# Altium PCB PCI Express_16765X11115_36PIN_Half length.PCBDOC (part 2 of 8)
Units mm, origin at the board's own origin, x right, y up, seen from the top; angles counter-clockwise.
Board outline 178 x 110.97 mm, 10 copper layers (Top Layer, Int1 (GND), Int2 (Sign), Int3 (Sign), Int4 (PWR), Int5 (GND), Int6 (Sign), Int7 (Sign), Int8 (GND), Bottom Layer), stack 1.429 mm thick; 528 components, 525 nets, 2272 pads, 1491 vias.
Unrouted connection lines stored in the file: 373.
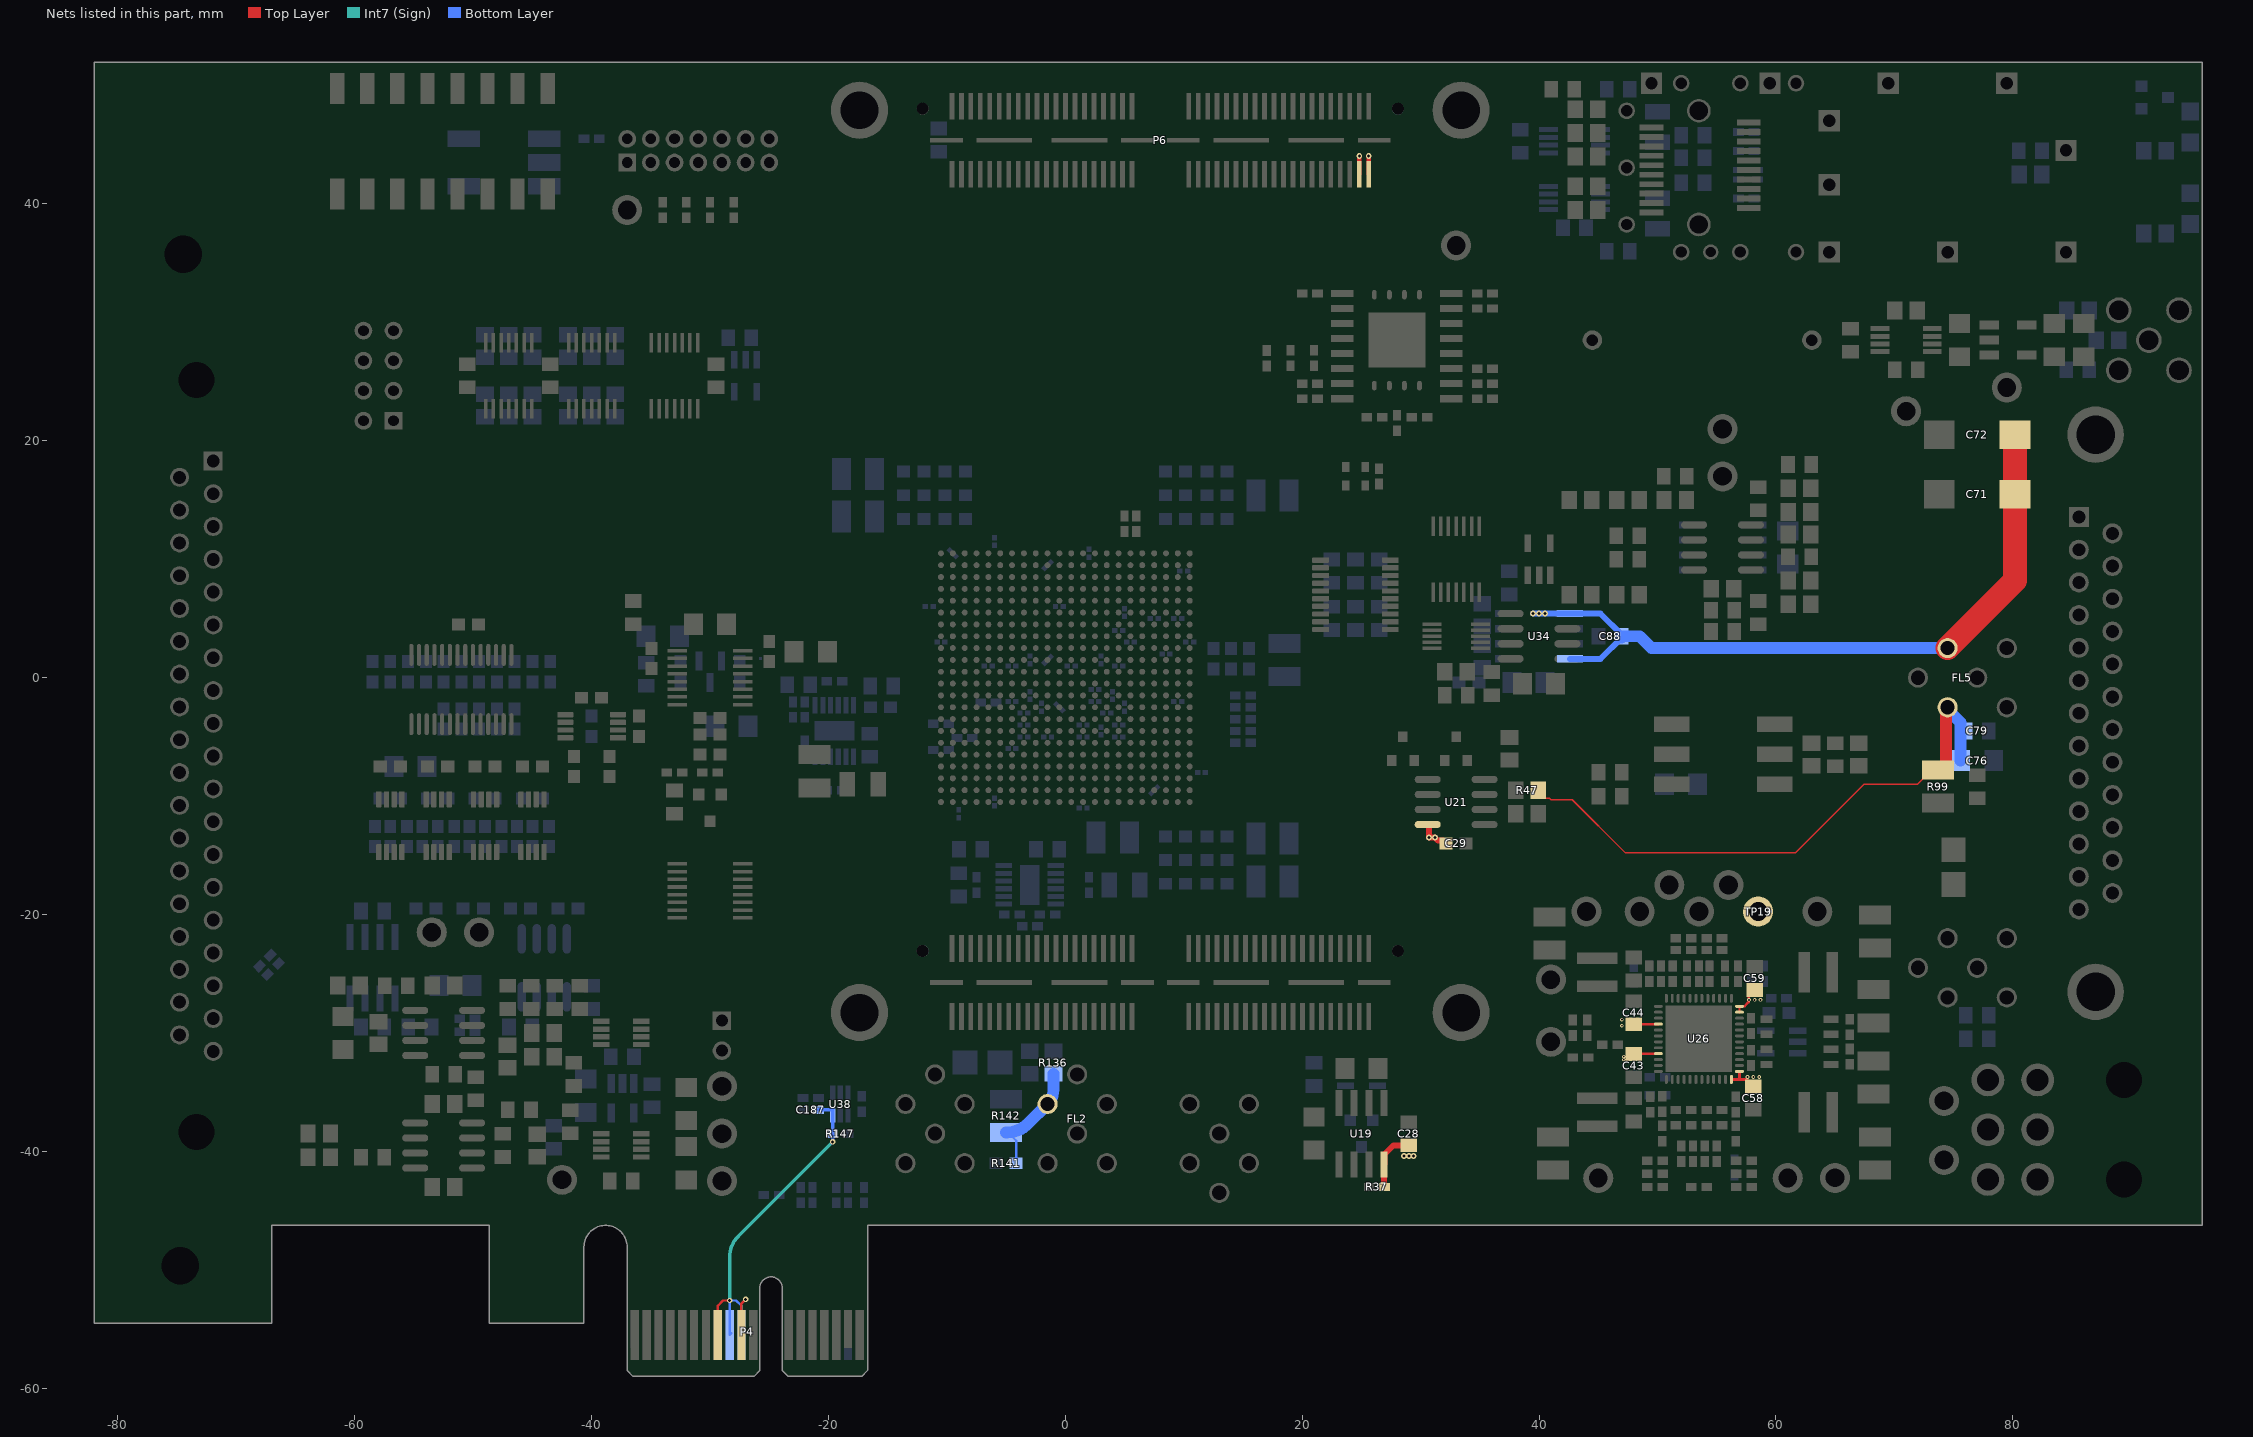
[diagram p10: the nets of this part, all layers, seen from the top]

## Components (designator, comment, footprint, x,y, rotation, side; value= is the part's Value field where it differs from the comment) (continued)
U10 "74LVC04" TSSOP14 -40,25.5 r0 top locked (schematic designator U25)
U11 "AD5060" SSO-G8/SM8 -37.5,-39.5 r270 top (schematic designator U45)
U12 "AD5060" SSO-G8/SM8 -37.5,-30 r270 top (schematic designator U14)
U13 "74LVC74D" TSSOP14 -33,25.5 r180 top (schematic designator U22)
U14 "SN65LVDT390" TSSOP16 -30,-18 r90 top (schematic designator U46)
U15 "SN74LVC4T245" TSSOP16 -30,0 r270 top (schematic designator U29)
U16 "XC7A35T-2FGG484C" FGG484 0,0 r90 top locked (schematic designator U18)
U17 "SN65LVDT14QPWREP" PW0020A_N 24.5,7 r0 top (schematic designator U6)
U18 "S25FL128SAGMFI001" FP-002-15547-MFG 28,28 r180 top locked (schematic designator U13)
U19 "LTC1144" SO-G8 25,-38.5 r180 top (schematic designator U50)
U20 "S25FL128SAGNFI003" SPSN-WSON-8_L 28,28.5 r270 top locked (schematic designator U16)
U21 "OP284ES" ADI-R-8_N 33,-10.5 r180 top (schematic designator U34)
U22 "AD7685" TSSO3x5-G10 33,3.5 r90 top (schematic designator U7)
U23 "74LVC74D" TSSOP14 33,10 r180 top (schematic designator U9)
U24 "OP284ES" SO-8_N 40,3.5 r180 top (schematic designator U5)
U25 "SN74LVC1G00" SO-G5/E2.4 40,10 r0 top (schematic designator U12)
U26 "ADP5050ACPZ-R7" CP-48-13_L 53.5,-30.5 r0 top value=Value (schematic designator U31)
U27 "33.554432MHz" VECTRON_C5310 59.9,-9 r180 top (schematic designator U10)
U28 "OP284ES" SO-8_N 55.5,11 r0 top (schematic designator U11)
U29 "SN65LVDS100D" MSOP8 71,28.5 r90 top (schematic designator U17)
U30 "SN65LVDT2" SO-G5/E2.4 60.5,-30.75 r270 bottom (schematic designator U15)
U31 "ADR425BR" SO-G8 55.5,11 r270 bottom (schematic designator U3)
U32 "SN65LVDS100D" MSOP8 43,45.3 r270 bottom (schematic designator U4)
U33 "SN65LVDT101D" MSOP8 43,40.5 r90 bottom (schematic designator U8)
U34 "LT1763" SO-G8 40,3.5 r90 bottom (schematic designator U1)
U35 "SN65LVDT2" SO-G5/E2.4 25,-33.5 r90 bottom (schematic designator U30)
U36 "LT3045" MSOP12_PAD -3,-17.5 r180 bottom (schematic designator U19)
U37 "LT3045" MSOP12_PAD -19.5,-4.5 r90 bottom locked (schematic designator U20)
U38 "SN74AVC1T45" SC70 -19,-36 r0 bottom (schematic designator U23)
U39 "SN65LVDT2" SO-G5/E2.4 -27,25.5 r0 bottom (schematic designator U24)
U40 "REF3033AIDBZRG4" TI-DBZ3_N -30,0.5 r270 bottom (schematic designator U33)
U41 "LT1964ES5-5" LT-S5-5-TSOT-23_M -37.4,-35.5 r270 bottom (schematic designator U49)
U42 "ADR421ARZ" ADI-R-8_M -44,-24.5 r270 bottom (schematic designator U51)
U43 "LT1763" SO-G8 -58.5,-24.5 r180 bottom (schematic designator U48)
W1 "Net tie" NETTIE1_BOTH -29,-28.96 r270 top net-tie (schematic designator W2)
W2 "Net tie" NETTIE1_SMDTOP -25.75,1.625 r0 bottom net-tie (schematic designator W3)
Y1 "DSC1001DI1-025.0000T" FP-CDFN2520-4LD-PL-1-MFG 24.493,17.003 r270 top

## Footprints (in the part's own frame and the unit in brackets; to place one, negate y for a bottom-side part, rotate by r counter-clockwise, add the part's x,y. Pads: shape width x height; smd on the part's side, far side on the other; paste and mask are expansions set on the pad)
2MM_HDR2X7_RA [mm] "Connector; 2mm Header; 7x2 Position, RA"
  rect 1.5x1.5 hole 0.9: 1(0,0)
  round 1.5 hole 0.9: 2(0,2) 3(2,0) 4(2,2) 5(4,0) 6(4,2) 7(6,0) 8(6,2) 9(8,0) 10(8,2) 11(10,0) 12(10,2) 13(12,0) 14(12,2)
  silkscreen extent -2.29,-1.27 14.22,8.38, body extent -2.32,-0.27 14.33,8.38, height 6.3
455580003 [mm]
  round 2.775 hole 1.85: 1(0,0) 2(4.191,0) 3(8.4,0) 4(0,-4.2) 5(4.2,-4.2) 6(8.4,-4.2)
  round 1.525 hole 3.05 unplated: MH1(0,7.3) MH2(8.4,7.3)
  silkscreen extent -2.7,1.1 11.1,13.9, body extent -3.14,-4.78 11.06,13.86, height 11.53
9181089621 [mm] "Connector; IDC, PCB Transition - 2 Rows, Thru-Hole; 8 Position; Vertical; Pitch 2.54 mm; Body 15.46 x 6.1 x 7.45 mm (LxWxH)"
  rect 1.5x1.5 hole 0.9: 1(-3.81,-1.27)
  round 1.5 hole 0.9: 2(-3.81,1.27) 3(-1.27,-1.27) 4(-1.27,1.27) 5(1.27,-1.27) 6(1.27,1.27) 7(3.81,-1.27) 8(3.81,1.27)
  silkscreen extent -7.73,-3.83 7.73,3.05
ADI-R-8_M [mm] "SOIC, 8-Leads, Body 4.9x3.9mm, Pitch 1.27mm, IPC Low Density"
  oval 2.5x0.7 smd: 1(-2.45,1.905) 2(-2.45,0.635) 3(-2.45,-0.635) 4(-2.45,-1.905) 5(2.45,-1.905) 6(2.45,-0.635) 7(2.45,0.635) 8(2.45,1.905)
  silkscreen extent -2.57,-2.5 0.8,2.93, body extent -2,-2.5 2,2.5, height 1.75
ADI-R-8_N [mm] "SOIC, 8-Leads, Body 4.9x3.9mm, Pitch 1.27mm, IPC Medium Density"
  oval 2.2x0.6 smd: 1(-2.4,1.905) 2(-2.4,0.635) 3(-2.4,-0.635) 4(-2.4,-1.905) 5(2.4,-1.905) 6(2.4,-0.635) 7(2.4,0.635) 8(2.4,1.905)
  silkscreen extent -2.53,-2.5 0.9,2.88, body extent -2,-2.5 2,2.5, height 1.75
ADI-RU-28_M [mm] "SOP, 28-Leads, Body 9.7x4.4mm, Pitch 0.65mm, IPC Low Density"
  oval 1.85x0.35 smd: 1(-2.925,4.225) 2(-2.925,3.575) 3(-2.925,2.925) 4(-2.925,2.275) 5(-2.925,1.625) 6(-2.925,0.975) 7(-2.925,0.325) 8(-2.925,-0.325) 9(-2.925,-0.975) 10(-2.925,-1.625) 11(-2.925,-2.275) 12(-2.925,-2.925) 13(-2.925,-3.575) 14(-2.925,-4.225) 15(2.925,-4.225) 16(2.925,-3.575) 17(2.925,-2.925) 18(2.925,-2.275) 19(2.925,-1.625) 20(2.925,-0.975) 21(2.925,-0.325) 22(2.925,0.325) 23(2.925,0.975) 24(2.925,1.625) 25(2.925,2.275) 26(2.925,2.925) 27(2.925,3.575) 28(2.925,4.225)
  silkscreen extent -3.05,-4.9 1.6,5.08, body extent -2.25,-4.9 2.25,4.9, height 1.2
AT224-3 [mil] "Mini-Circuits transformer"
  rect 65x30 smd: 1(0,-100) 2(0,-50) 3(0,0) 4(125,0) 6(125,-100)
  silkscreen extent 25,-135 100,-135, body extent 0,-125 125,25, height 150
CA053035 [mil] "Axial film capacitor, Size 0.53\"(L) x 0.35\"(D)"
  round 65 hole 38: 1(0,0) 2(730,0)
  silkscreen extent 40,-175 690,175, body extent 80,-175 650,175, height 360
CAPC0603X33X15NL03T05 [mm] "Chip Capacitor, 2-Leads, Body 0.60x0.30mm, IPC Medium Density"
  rect 0.46x0.42 smd: 1(-0.33,0) 2(0.33,0)
  body extent -0.31,-0.17 0.32,0.16, height 0.33
CC1005-0402 [mm] "Chip Capacitor; Body 1.0 x 0.5 mm (LxW typ)"
  rect 0.9x0.7 smd: 1(-0.65,0) 2(0.65,0)
  silkscreen extent -1.4,-0.25 -1.4,0.25, body extent -0.53,-0.28 0.52,0.27, height 0.55
CC1608-0603 [mm] "Chip Capacitor; Body 1.6 x 0.8 mm (LxW typ)"
  rect 1.1x1 smd: 1(-0.85,0) 2(0.85,0)
  silkscreen extent -1.7,-0.4 -1.7,0.4, body extent -0.87,-0.48 0.87,0.48, height 0.87
CC2013-0805 [mm] "Chip Capacitor; Body 2.0 x 1.3 mm (LxW typ)"
  rect 1.15x1.4 smd: 1(-0.975,0) 2(0.975,0)
  silkscreen extent -1.85,-0.6 -1.85,0.6, body extent -1.1,-0.73 1.1,0.72, height 0.88
CC3216-1206 [mm] "Chip Capacitor; Body 3.2 x 1.6 mm (LxW typ)"
  rect 1.6x1.8 smd: 1(-1.4,0) 2(1.4,0)
  silkscreen extent -0.3,-0.8 0.3,0.8, body extent -1.85,-0.98 1.85,0.97, height 0.88
CC3225-1210 [mm] "Chip Capacitor; Body 3.2 x 2.5 mm (LxW typ)"
  rect 1.6x2.7 smd: 1(-1.4,0) 2(1.4,0)
  silkscreen extent -0.3,-1.25 0.3,1.25, body extent -1.85,-1.45 1.85,1.45, height 1.4
CL2520-1008 [mm] "Chip Inductor; Body 2.54 x 2.0 mm (LxW typ)"
  rect 1.3x2.1 smd: 1(-1.3,0) 2(1.3,0)
  silkscreen extent -2.25,-1 -2.25,1, body extent -1.46,-1.39 1.46,1.4, height 2.02
CP-48-13_L [mm] "QFN, 48-Leads, Body 7x7mm, Pitch 0.5mm, Thermal Pad 5.6x5.6mm, IPC High Density"
  oval 0.75x0.25 smd: 1(-3.425,2.75) 2(-3.425,2.25) 3(-3.425,1.75) 4(-3.425,1.25) 5(-3.425,0.75) 6(-3.425,0.25) 7(-3.425,-0.25) 8(-3.425,-0.75) 9(-3.425,-1.25) 10(-3.425,-1.75) 11(-3.425,-2.25) 12(-3.425,-2.75) 25(3.425,-2.75) 26(3.425,-2.25) 27(3.425,-1.75) 28(3.425,-1.25) 29(3.425,-0.75) 30(3.425,-0.25) 31(3.425,0.25) 32(3.425,0.75) 33(3.425,1.25) 34(3.425,1.75) 35(3.425,2.25) 36(3.425,2.75)
  oval 0.25x0.75 smd: 13(-2.75,-3.425) 14(-2.25,-3.425) 15(-1.75,-3.425) 16(-1.25,-3.425) 17(-0.75,-3.425) 18(-0.25,-3.425) 19(0.25,-3.425) 20(0.75,-3.425) 21(1.25,-3.425) 22(1.75,-3.425) 23(2.25,-3.425) 24(2.75,-3.425) 37(2.75,3.425) 38(2.25,3.425) 39(1.75,3.425) 40(1.25,3.425) 41(0.75,3.425) 42(0.25,3.425) 43(-0.25,3.425) 44(-0.75,3.425) 45(-1.25,3.425) 46(-1.75,3.425) 47(-2.25,3.425) 48(-2.75,3.425)
  rect 5.6x5.6 smd: 49(0,0)
  silkscreen extent -4.47,-3.7 3.7,3.7, body extent -3.55,-3.55 3.55,3.55, height 0.8
CR1005-0402 [mm] "Chip Resistor; Body 1.1 x 0.5 mm (LxW typ)"
  rect 0.9x0.7 smd: 1(-0.65,0) 2(0.65,0)
  body extent -0.5,-0.25 0.5,0.25, height 0.32
CR1608-0603 [mm] "Chip Resistor; Body 1.6 x 0.8 mm (LxW typ)"
  rect 1.1x1 smd: 1(-0.85,0) 2(0.85,0)
  body extent -0.76,-0.43 0.79,0.42, height 0.46
CR2012-0805 [mm] "Chip Resistor; Body 2.0 x 1.3 mm (LxW typ)"
  rect 1.3x1.5 smd: 1(-0.95,0) 2(0.95,0)
  body extent -1,-0.62 1,0.63, height 0.46
CR3216-1206 [mm] "Chip Resistor; Body 3.2 x 1.6 mm (LxW typ)"
  rect 1.6x1.8 smd: 1(-1.4,0) 2(1.4,0)
  silkscreen extent -0.3,-0.8 0.3,0.8, body extent -1.67,-0.86 1.68,0.87, height 0.85
CR3225-1210 [mm] "Chip Resistor; Body 3.2 x 2.5 mm (LxW typ)"
  rect 1.6x2.7 smd: 1(-1.4,0) 2(1.4,0)
  silkscreen extent -0.3,-1.25 0.3,1.25, body extent -1.73,-1.37 1.73,1.37, height 0.71
DB25F-RA [mm] "Receptiacle; D Subminiature 25 Position; Right Angle"
  rect 1.69x1.69 hole 1.09: 1(-16.566,-1.42)
  round 1.69 hole 1.09: 2(-13.805,-1.42) 3(-11.044,-1.42) 4(-8.283,-1.42) 5(-5.522,-1.42) 6(-2.761,-1.42) 7(0,-1.42) 8(2.761,-1.42) 9(5.522,-1.42) 10(8.283,-1.42) 11(11.044,-1.42) 12(13.805,-1.42) 13(16.566,-1.42) 14(-15.185,1.42) 15(-12.424,1.42) 16(-9.663,1.42) 17(-6.902,1.42) 18(-4.142,1.42) 19(-1.381,1.42) 20(1.381,1.42) 21(4.142,1.42) 22(6.903,1.42) 23(9.664,1.42) 24(12.425,1.42) 25(15.186,1.42)
  round 4.76 hole 3.26: 26(-23.526,0) 27(23.526,0)
  silkscreen extent -26.5,-3 26.6,9.5, body extent -26.59,-3.18 26.49,15.72, height 12.62
DGK0008A_N [mm] "TSOP, 8-Leads, Body 3.1x3.1mm, Pitch 0.65mm, IPC Medium Density"
  rrect22% 1.35x0.45 smd: 1(-2.225,0.975) 2(-2.225,0.325) 3(-2.225,-0.325) 4(-2.225,-0.975) 5(2.225,-0.975) 6(2.225,-0.325) 7(2.225,0.325) 8(2.225,0.975)
  silkscreen extent -2.35,-1.55 1.15,1.9, body extent -2.45,-1.5 2.45,1.5, height 0.94
DIP_SW_8WAY_SMD_SIDE [mm] "DIP Switch; 16 Leads, right-angle"
  rect 1.2x2.6 smd: 1(-8.89,-4.45) 2(-6.35,-4.45) 3(-3.81,-4.45) 4(-1.27,-4.45) 5(1.27,-4.45) 6(3.81,-4.45) 7(6.35,-4.45) 8(8.89,-4.45) 9(8.89,4.45) 10(6.35,4.45) 11(3.81,4.45) 12(1.27,4.45) 13(-1.27,4.45) 14(-3.81,4.45) 15(-6.35,4.45) 16(-8.89,4.45)
  silkscreen extent -10.29,-2.5 10.31,2.5, body extent -11.15,-6.5 11.15,4.65, height 6.98
FGG484 [mm] "BGA, 484-Balls, Body 23x23mm, Pitch 1mm"
  round 0.5 smd: A1(-10.5,10.5) A2(-9.5,10.5) A3(-8.5,10.5) A4(-7.5,10.5) A5(-6.5,10.5) A6(-5.5,10.5) A7(-4.5,10.5) A8(-3.5,10.5) A9(-2.5,10.5) A10(-1.5,10.5) A11(-0.5,10.5) A12(0.5,10.5) A13(1.5,10.5) A14(2.5,10.5) A15(3.5,10.5) A16(4.5,10.5) A17(5.5,10.5) A18(6.5,10.5) A19(7.5,10.5) A20(8.5,10.5) A21(9.5,10.5) A22(10.5,10.5) AA1(-10.5,-9.5) AA2(-9.5,-9.5) AA3(-8.5,-9.5) AA4(-7.5,-9.5) AA5(-6.5,-9.5) AA6(-5.5,-9.5) AA7(-4.5,-9.5) AA8(-3.5,-9.5) AA9(-2.5,-9.5) AA10(-1.5,-9.5) AA11(-0.5,-9.5) AA12(0.5,-9.5) AA13(1.5,-9.5) AA14(2.5,-9.5) AA15(3.5,-9.5) AA16(4.5,-9.5) AA17(5.5,-9.5) AA18(6.5,-9.5) AA19(7.5,-9.5) AA20(8.5,-9.5) AA21(9.5,-9.5) AA22(10.5,-9.5) AB1(-10.5,-10.5) AB2(-9.5,-10.5) AB3(-8.5,-10.5) AB4(-7.5,-10.5) AB5(-6.5,-10.5) AB6(-5.5,-10.5) AB7(-4.5,-10.5) AB8(-3.5,-10.5) AB9(-2.5,-10.5) AB10(-1.5,-10.5) AB11(-0.5,-10.5) AB12(0.5,-10.5) AB13(1.5,-10.5) AB14(2.5,-10.5) AB15(3.5,-10.5) AB16(4.5,-10.5) AB17(5.5,-10.5) AB18(6.5,-10.5) AB19(7.5,-10.5) AB20(8.5,-10.5) AB21(9.5,-10.5) AB22(10.5,-10.5) B1(-10.5,9.5) B2(-9.5,9.5) B3(-8.5,9.5) B4(-7.5,9.5) B5(-6.5,9.5) B6(-5.5,9.5) B7(-4.5,9.5) B8(-3.5,9.5) B9(-2.5,9.5) B10(-1.5,9.5) B11(-0.5,9.5) B12(0.5,9.5) B13(1.5,9.5) B14(2.5,9.5) B15(3.5,9.5) B16(4.5,9.5) B17(5.5,9.5) B18(6.5,9.5) B19(7.5,9.5) B20(8.5,9.5) B21(9.5,9.5) B22(10.5,9.5) C1(-10.5,8.5) C2(-9.5,8.5) C3(-8.5,8.5) C4(-7.5,8.5) C5(-6.5,8.5) C6(-5.5,8.5) C7(-4.5,8.5) C8(-3.5,8.5) C9(-2.5,8.5) C10(-1.5,8.5) C11(-0.5,8.5) C12(0.5,8.5) C13(1.5,8.5) C14(2.5,8.5) C15(3.5,8.5) C16(4.5,8.5) C17(5.5,8.5) C18(6.5,8.5) C19(7.5,8.5) C20(8.5,8.5) C21(9.5,8.5) C22(10.5,8.5) D1(-10.5,7.5) D2(-9.5,7.5) D3(-8.5,7.5) D4(-7.5,7.5) D5(-6.5,7.5) D6(-5.5,7.5) D7(-4.5,7.5) D8(-3.5,7.5) D9(-2.5,7.5) D10(-1.5,7.5) D11(-0.5,7.5) D12(0.5,7.5) D13(1.5,7.5) D14(2.5,7.5) D15(3.5,7.5) D16(4.5,7.5) D17(5.5,7.5) D18(6.5,7.5) D19(7.5,7.5) D20(8.5,7.5) D21(9.5,7.5) D22(10.5,7.5) E1(-10.5,6.5) E2(-9.5,6.5) E3(-8.5,6.5) E4(-7.5,6.5) E5(-6.5,6.5) E6(-5.5,6.5) E7(-4.5,6.5) E8(-3.5,6.5) E9(-2.5,6.5) E10(-1.5,6.5) E11(-0.5,6.5) E12(0.5,6.5) E13(1.5,6.5) E14(2.5,6.5) E15(3.5,6.5) E16(4.5,6.5) E17(5.5,6.5) E18(6.5,6.5) E19(7.5,6.5) E20(8.5,6.5) E21(9.5,6.5) E22(10.5,6.5) F1(-10.5,5.5) F2(-9.5,5.5) F3(-8.5,5.5) F4(-7.5,5.5) F5(-6.5,5.5) F6(-5.5,5.5) F7(-4.5,5.5) F8(-3.5,5.5) F9(-2.5,5.5) F10(-1.5,5.5) F11(-0.5,5.5) F12(0.5,5.5) F13(1.5,5.5) F14(2.5,5.5) F15(3.5,5.5) F16(4.5,5.5) F17(5.5,5.5) F18(6.5,5.5) F19(7.5,5.5) F20(8.5,5.5) F21(9.5,5.5) F22(10.5,5.5) G1(-10.5,4.5) G2(-9.5,4.5) G3(-8.5,4.5) G4(-7.5,4.5) G5(-6.5,4.5) G6(-5.5,4.5) G7(-4.5,4.5) G8(-3.5,4.5) G9(-2.5,4.5) G10(-1.5,4.5) G11(-0.5,4.5) G12(0.5,4.5) G13(1.5,4.5) G14(2.5,4.5) G15(3.5,4.5) G16(4.5,4.5) G17(5.5,4.5) G18(6.5,4.5) G19(7.5,4.5) G20(8.5,4.5) G21(9.5,4.5) G22(10.5,4.5) H1(-10.5,3.5) H2(-9.5,3.5) H3(-8.5,3.5) H4(-7.5,3.5) H5(-6.5,3.5) H6(-5.5,3.5) H7(-4.5,3.5) H8(-3.5,3.5) H9(-2.5,3.5) H10(-1.5,3.5) H11(-0.5,3.5) H12(0.5,3.5) H13(1.5,3.5) H14(2.5,3.5) H15(3.5,3.5) H16(4.5,3.5) H17(5.5,3.5) H18(6.5,3.5) H19(7.5,3.5) H20(8.5,3.5) H21(9.5,3.5) H22(10.5,3.5) J1(-10.5,2.5) J2(-9.5,2.5) J3(-8.5,2.5) J4(-7.5,2.5) J5(-6.5,2.5) J6(-5.5,2.5) J7(-4.5,2.5) J8(-3.5,2.5) J9(-2.5,2.5) J10(-1.5,2.5) J11(-0.5,2.5) J12(0.5,2.5) J13(1.5,2.5) J14(2.5,2.5) J15(3.5,2.5) J16(4.5,2.5) J17(5.5,2.5) J18(6.5,2.5) J19(7.5,2.5) J20(8.5,2.5) J21(9.5,2.5) J22(10.5,2.5) K1(-10.5,1.5) K2(-9.5,1.5) K3(-8.5,1.5) K4(-7.5,1.5) K5(-6.5,1.5) K6(-5.5,1.5) K7(-4.5,1.5) K8(-3.5,1.5) K9(-2.5,1.5) K10(-1.5,1.5) K11(-0.5,1.5) K12(0.5,1.5) K13(1.5,1.5) K14(2.5,1.5) K15(3.5,1.5) K16(4.5,1.5) K17(5.5,1.5) K18(6.5,1.5) K19(7.5,1.5) K20(8.5,1.5) K21(9.5,1.5) K22(10.5,1.5) L1(-10.5,0.5) L2(-9.5,0.5) L3(-8.5,0.5) L4(-7.5,0.5) L5(-6.5,0.5) L6(-5.5,0.5) L7(-4.5,0.5) L8(-3.5,0.5) L9(-2.5,0.5) L10(-1.5,0.5) L11(-0.5,0.5) L12(0.5,0.5) L13(1.5,0.5) L14(2.5,0.5) L15(3.5,0.5) L16(4.5,0.5) L17(5.5,0.5) L18(6.5,0.5) L19(7.5,0.5) L20(8.5,0.5) L21(9.5,0.5) L22(10.5,0.5) M1(-10.5,-0.5) M2(-9.5,-0.5) M3(-8.5,-0.5) M4(-7.5,-0.5) M5(-6.5,-0.5) M6(-5.5,-0.5) M7(-4.5,-0.5) M8(-3.5,-0.5) M9(-2.5,-0.5) M10(-1.5,-0.5) M11(-0.5,-0.5) M12(0.5,-0.5) M13(1.5,-0.5) M14(2.5,-0.5) M15(3.5,-0.5) M16(4.5,-0.5) M17(5.5,-0.5) M18(6.5,-0.5) M19(7.5,-0.5) M20(8.5,-0.5) M21(9.5,-0.5) M22(10.5,-0.5) N1(-10.5,-1.5) N2(-9.5,-1.5) N3(-8.5,-1.5) N4(-7.5,-1.5) N5(-6.5,-1.5) N6(-5.5,-1.5) N7(-4.5,-1.5) N8(-3.5,-1.5) N9(-2.5,-1.5) N10(-1.5,-1.5) N11(-0.5,-1.5) N12(0.5,-1.5) N13(1.5,-1.5) N14(2.5,-1.5) N15(3.5,-1.5) N16(4.5,-1.5) N17(5.5,-1.5) N18(6.5,-1.5) N19(7.5,-1.5) N20(8.5,-1.5) N21(9.5,-1.5) N22(10.5,-1.5) P1(-10.5,-2.5) P2(-9.5,-2.5) P3(-8.5,-2.5) P4(-7.5,-2.5) P5(-6.5,-2.5) P6(-5.5,-2.5) P7(-4.5,-2.5) P8(-3.5,-2.5) P9(-2.5,-2.5) P10(-1.5,-2.5) P11(-0.5,-2.5) P12(0.5,-2.5) P13(1.5,-2.5) P14(2.5,-2.5) P15(3.5,-2.5) P16(4.5,-2.5) P17(5.5,-2.5) P18(6.5,-2.5) P19(7.5,-2.5) P20(8.5,-2.5) P21(9.5,-2.5) P22(10.5,-2.5) R1(-10.5,-3.5) R2(-9.5,-3.5) R3(-8.5,-3.5) R4(-7.5,-3.5) R5(-6.5,-3.5) R6(-5.5,-3.5) R7(-4.5,-3.5) R8(-3.5,-3.5) R9(-2.5,-3.5) R10(-1.5,-3.5) R11(-0.5,-3.5) R12(0.5,-3.5) R13(1.5,-3.5) R14(2.5,-3.5) R15(3.5,-3.5) R16(4.5,-3.5) R17(5.5,-3.5) R18(6.5,-3.5) R19(7.5,-3.5) R20(8.5,-3.5) R21(9.5,-3.5) R22(10.5,-3.5) T1(-10.5,-4.5) T2(-9.5,-4.5) T3(-8.5,-4.5) T4(-7.5,-4.5) T5(-6.5,-4.5) T6(-5.5,-4.5) T7(-4.5,-4.5) T8(-3.5,-4.5) T9(-2.5,-4.5) T10(-1.5,-4.5) T11(-0.5,-4.5) T12(0.5,-4.5) T13(1.5,-4.5) T14(2.5,-4.5) T15(3.5,-4.5) T16(4.5,-4.5) T17(5.5,-4.5) T18(6.5,-4.5) T19(7.5,-4.5) T20(8.5,-4.5) T21(9.5,-4.5) T22(10.5,-4.5) U1(-10.5,-5.5) U2(-9.5,-5.5) U3(-8.5,-5.5) U4(-7.5,-5.5) U5(-6.5,-5.5) U6(-5.5,-5.5) U7(-4.5,-5.5) U8(-3.5,-5.5) U9(-2.5,-5.5) U10(-1.5,-5.5) U11(-0.5,-5.5) U12(0.5,-5.5) U13(1.5,-5.5) U14(2.5,-5.5) U15(3.5,-5.5) U16(4.5,-5.5) U17(5.5,-5.5) U18(6.5,-5.5) U19(7.5,-5.5) U20(8.5,-5.5) U21(9.5,-5.5) U22(10.5,-5.5) V1(-10.5,-6.5) V2(-9.5,-6.5) V3(-8.5,-6.5) V4(-7.5,-6.5) V5(-6.5,-6.5) V6(-5.5,-6.5) V7(-4.5,-6.5) V8(-3.5,-6.5) V9(-2.5,-6.5) V10(-1.5,-6.5) V11(-0.5,-6.5) V12(0.5,-6.5) V13(1.5,-6.5) V14(2.5,-6.5) V15(3.5,-6.5) V16(4.5,-6.5) V17(5.5,-6.5) V18(6.5,-6.5) V19(7.5,-6.5) V20(8.5,-6.5) V21(9.5,-6.5) V22(10.5,-6.5) W1(-10.5,-7.5) W2(-9.5,-7.5) W3(-8.5,-7.5) W4(-7.5,-7.5) W5(-6.5,-7.5) W6(-5.5,-7.5) W7(-4.5,-7.5) W8(-3.5,-7.5) W9(-2.5,-7.5) W10(-1.5,-7.5) W11(-0.5,-7.5) W12(0.5,-7.5) W13(1.5,-7.5) W14(2.5,-7.5) W15(3.5,-7.5) W16(4.5,-7.5) W17(5.5,-7.5) W18(6.5,-7.5) W19(7.5,-7.5) W20(8.5,-7.5) W21(9.5,-7.5) W22(10.5,-7.5) Y1(-10.5,-8.5) Y2(-9.5,-8.5) Y3(-8.5,-8.5) Y4(-7.5,-8.5) Y5(-6.5,-8.5) Y6(-5.5,-8.5) Y7(-4.5,-8.5) Y8(-3.5,-8.5) Y9(-2.5,-8.5) Y10(-1.5,-8.5) Y11(-0.5,-8.5) Y12(0.5,-8.5) Y13(1.5,-8.5) Y14(2.5,-8.5) Y15(3.5,-8.5) Y16(4.5,-8.5) Y17(5.5,-8.5) Y18(6.5,-8.5) Y19(7.5,-8.5) Y20(8.5,-8.5) Y21(9.5,-8.5) Y22(10.5,-8.5)
  silkscreen extent -12.27,-11.5 11.5,11.5, body extent -11.5,-11.5 11.5,11.5, height 2.6
FP-002-15547-MFG [mm]
  rect 1.9x0.6 smd: 1(-4.6,4.445) 2(-4.6,3.175) 3(-4.6,1.905) 4(-4.6,0.635) 5(-4.6,-0.635) 6(-4.6,-1.905) 7(-4.6,-3.175) 8(-4.6,-4.445) 9(4.6,-4.445) 10(4.6,-3.175) 11(4.6,-1.905) 12(4.6,-0.635) 13(4.6,0.635) 14(4.6,1.905) 15(4.6,3.175) 16(4.6,4.445)
  silkscreen extent -6.25,-5.25 2.8,5.25, body extent -5.65,-5.5 5.65,5.5, height 0.25
FP-CDFN2520-4LD-PL-1-MFG [mm]
  rect 0.85x0.65 smd paste+0 mask+0: 1(-0.775,0.825) 2(-0.775,-0.825) 3(0.775,-0.825) 4(0.775,0.825)
  silkscreen extent -1.92,-0.13 1.02,0.95, body extent -1.3,-1.38 1.3,1.38, height 0.25
FP-XAL40-MFG [mm]
  rect 0.98x3.4 smd: 1(-1.185,0) 2(1.185,0)
  silkscreen extent -2.15,-2.15 2.15,2.15, body extent -2.25,-2.25 2.25,2.25, height 0.25
KING-LED2107-13-RED-2_V [mm] "LED, Right Angle SMT, 2.1x0.7mm, 1.3mm Thickness, Pad 1 Cathode"
  rect 1.5x1.5 smd paste+0 mask+0: 1(1.3,0) 2(-1.3,0)
  silkscreen extent 2.35,-0.64 2.35,0.63, body extent -1.05,-0.4 1.05,0.9, height 0.67
LED-0805 [mm] "SMD LED, 805, Body 2.0 x 1.3 mm (LxW typ)"
  rect 1.15x1.4 smd: 1(-0.975,0) 2(0.975,0)
  silkscreen extent -1.85,-0.6 -1.85,0.6, body extent -1,-0.62 1,0.63, height 0.75
LIGO-LOGO-SM [mm] "Smaller Ligo Logo"
  silkscreen extent -3.92,0.1 -0.92,3.1
LT-S5-5-TSOT-23_M [mm] "SOT23, 5-Leads, Body 2.90x1.63mm, Pitch 0.95mm, IPC Low Density"
  rect 1.6x0.65 smd: 1(-1.25,0.95) 2(-1.25,0) 3(-1.25,-0.95) 4(1.25,-0.95) 5(1.25,0.95)
  silkscreen extent -1.37,-1.45 0.05,1.95, body extent -0.87,-1.45 0.87,1.45, height 1
MCSM-DO-214BA-2_L [mm] "Molded, 2-Leads, Body 4.57x3.94mm, IPC High Density"
  rect 2.1x2.05 smd: 1(-1.475,0) 2(1.475,0)
  silkscreen extent -2.3,-2 3.03,2, body extent -2.5,-1.97 2.51,1.97, height 3.3
MSA/SFP2x10 [mm] "Multi Source Agreement, Small Factor Plugable"
  rect 2x0.5 smd: 1(0,0) 2(0,-0.8) 3(0,-1.6) 4(0,-2.4) 5(0,-3.2) 6(0,-4) 7(0,-4.8) 8(0,-5.6) 9(0,-6.4) 10(0,-7.2) 11(8.2,-6.8) 12(8.2,-6) 13(8.2,-5.2) 14(8.2,-4.4) 15(8.2,-3.6) 16(8.2,-2.8) 17(8.2,-2) 18(8.2,-1.2) 19(8.2,-0.4) 20(8.2,0.4)
  rect 1.8x1.8 hole 1.05: 21(-26.8,-4.85) 21(-26.8,3.73) 21(-21.8,-10.53) 21(-16.8,3.73) 21(-11.8,-10.53) 21(-6.8,-1.95) 21(-6.8,3.73) 21(-6.8,-7.35) 21(-1.8,-10.53) 21(8.2,-10.53)
  round 1.4 hole 0.95: 22(-4,3.73) 22(-4,-10.53) 22(0.7,3.73) 22(0.7,-10.53) 22(5.7,3.73) 22(5.7,-10.53) 22(10.3,-3.4) 22(10.3,1.4) 22(10.3,-8.2)
  round 2 hole 1.55: 23(4.2,1.4) 23(4.2,-8.2)
  round 1.3 hole 0.85: 24(3.2,3.73)
  silkscreen extent -31.2,-11.43 10.9,4.63, body extent -38.26,-11.3 10.54,4.54, height 10.83
MSOP8 [mm] "MSOP Plastic Small-Outline Package"
  rect 0.42x1.6 smd: 1(-0.975,-2.205) 2(-0.325,-2.205) 3(0.325,-2.205) 4(0.975,-2.205) 5(0.975,2.195) 6(0.325,2.195) 7(-0.325,2.195) 8(-0.975,2.195)
  silkscreen extent -1.3,-0.77 1.3,0.76, body extent -1.5,-2.45 1.5,2.45, height 1.15
MSOP12_PAD [mil] "MSOP 12 with pad"
  rect 55x17 smd paste+0 mask+0: 1(-86,63.98) 2(-86,38.39) 3(-86,12.8) 4(-86,-12.8) 5(-86,-38.39) 6(-86,-63.98) 7(86,-63.98) 8(86,-38.39) 9(86,-12.8) 10(86,12.8) 11(86,38.39) 12(86,63.98)
  rect 65x133.86 smd paste-55.5 mask+0: 13(0,0)
  silkscreen extent -53,-84 134,84, body extent -99,-79 99,79, height 67
MURA-BNX016-01_V [mm] "THD, 6-Leads, Body 12x11mm"
  round 1.7 hole 1.2: 1(-2.5,2.5) 2(2.5,2.5) 3(-2.5,-2.5) 4(2.5,-2.5) 5(0,0) 6(0,5)
  silkscreen extent -6.29,-6 5.5,6, body extent -5.5,-6 5.5,6, height 8
NETTIE1_BOTH [mm] "Tie two nets together"
  rect 1.575x1.575 hole 1.016: 1(0,0)
  round 1.575 hole 1.016: 2(2.54,0)
  Top Layer region: -1.016,-1.016 3.556,-1.016 3.556,1.016 -1.016,1.016
  Bottom Layer region: -1.016,-1.016 3.556,-1.016 3.556,1.016 -1.016,1.016
NETTIE1_SMDTOP [mil] "Tie two nets together"
  rect 10x10 smd mask-10: 1(0,0) 2(20,0)
  Top Layer region: -10,10 30,10 30,-10 -10,-10
NORCO-182-037-113R531_V [mm] "Connector, 37-Leads, Body 69.317x12.954mm, Pitch 1.385mm"
  rect 1.6x1.6 hole 1.09: 1(-24.93,1.42)
  round 1.6 hole 1.09: 2(-22.16,1.42) 3(-19.39,1.42) 4(-16.62,1.42) 5(-13.85,1.42) 6(-11.08,1.42) 7(-8.31,1.42) 8(-5.54,1.42) 9(-2.77,1.42) 10(0,1.42) 11(2.77,1.42) 12(5.54,1.42) 13(8.31,1.42) 14(11.08,1.42) 15(13.85,1.42) 16(16.62,1.42) 17(19.39,1.42) 18(22.16,1.42) 19(24.93,1.42) 20(-23.545,-1.42) 21(-20.775,-1.42) 22(-18.005,-1.42) 23(-15.235,-1.42) 24(-12.465,-1.42) 25(-9.695,-1.42) 26(-6.925,-1.42) 27(-4.155,-1.42) 28(-1.385,-1.42) 29(1.385,-1.42) 30(4.155,-1.42) 31(6.925,-1.42) 32(9.695,-1.42) 33(12.465,-1.42) 34(15.235,-1.42) 35(18.005,-1.42) 36(20.775,-1.42) 37(23.545,-1.42)
  round 0 hole 3.05: S1(-31.75,0) S2(31.75,0)
  silkscreen extent -34.77,-9.5 34.54,4.13, body extent -34.77,-15.7 34.54,3.45, height 12.56
ONSC-SOT-23-3-318-08_V [mm] "SOT23, 3-Leads, Body 2.92x1.3mm, Pitch 0.95mm"
  rect 0.9x0.8 smd: 1(-1,0.95) 2(-1,-0.95) 3(1,0)
  silkscreen extent -1.12,-1.46 0.65,2.02, body extent -0.65,-1.46 0.65,1.46, height 1.11
PCIeX1-GF-2D-1000-1K-O36 [mm] "Golden finger, PCIeX1, Dual, Opposite, Pitch 1mm, 36-Position"
  rect 0.7x3.2 smd far side: A1(-9.5,0.5)
  rect 0.7x4.2 smd far side: A2(-8.5,0) A3(-7.5,0) A4(-6.5,0) A5(-5.5,0) A6(-4.5,0) A7(-3.5,0) A8(-2.5,0) A9(-1.5,0) A10(-0.5,0) A11(0.5,0) A12(3.5,0) A13(4.5,0) A14(5.5,0) A15(6.5,0) A16(7.5,0) A17(8.5,0) A18(9.5,0)
  rect 0.7x4.2 smd: B1(-9.5,0) B2(-8.5,0) B3(-7.5,0) B4(-6.5,0) B5(-5.5,0) B6(-4.5,0) B7(-3.5,0) B8(-2.5,0) B9(-1.5,0) B10(-0.5,0) B11(0.5,0) B12(3.5,0) B13(4.5,0) B14(5.5,0) B15(6.5,0) B16(7.5,0) B18(9.5,0)
  rect 0.7x3.2 smd: B17(8.5,0.5)
PW0020A_N [mm] "SOP, 20-Leads, Body 6.6x4.5mm, Pitch 0.65mm, IPC Medium Density"
  rrect22% 1.4x0.45 smd: 1(-2.95,2.925) 2(-2.95,2.275) 3(-2.95,1.625) 4(-2.95,0.975) 5(-2.95,0.325) 6(-2.95,-0.325) 7(-2.95,-0.975) 8(-2.95,-1.625) 9(-2.95,-2.275) 10(-2.95,-2.925) 11(2.95,-2.925) 12(2.95,-2.275) 13(2.95,-1.625) 14(2.95,-0.975) 15(2.95,-0.325) 16(2.95,0.325) 17(2.95,0.975) 18(2.95,1.625) 19(2.95,2.275) 20(2.95,2.925)
  silkscreen extent -3.07,-3.3 1.85,3.82, body extent -3.21,-3.25 3.21,3.25, height 1
QSE040 [mil] "Samtec hi-speed socket, 0.8mm, QSE series, 80 pins"
  rect 16x89 smd: 1(-692.9,-112.78) 2(-692.9,112.78) 3(-661.42,-112.78) 4(-661.42,112.78) 5(-629.92,-112.78) 6(-629.92,112.78) 7(-598.42,-112.78) 8(-598.42,112.78) 9(-566.92,-112.78) 10(-566.92,112.78) 11(-535.42,-112.78) 12(-535.42,112.78) 13(-503.93,-112.78) 14(-503.93,112.78) 15(-472.43,-112.78) 16(-472.43,112.78) 17(-440.93,-112.78) 18(-440.93,112.78) 19(-409.43,-112.78) 20(-409.43,112.78) 21(-377.95,-112.78) 22(-377.95,112.78) 23(-346.45,-112.78) 24(-346.45,112.78) 25(-314.95,-112.78) 26(-314.95,112.78) 27(-283.45,-112.78) 28(-283.45,112.78) 29(-251.97,-112.78) 30(-251.97,112.78) 31(-220.47,-112.78) 32(-220.47,112.78) 33(-188.97,-112.78) 34(-188.97,112.78) 35(-157.47,-112.78) 36(-157.47,112.78) 37(-125.98,-112.78) 38(-125.98,112.78) 39(-94.48,-112.78) 40(-94.48,112.78) 41(94.48,-112.78) 42(94.48,112.78) 43(125.98,-112.78) 44(125.98,112.78) 45(157.47,-112.78) 46(157.47,112.78) 47(188.97,-112.78) 48(188.97,112.78) 49(220.47,-112.78) 50(220.47,112.78) 51(251.97,-112.78) 52(251.97,112.78) 53(283.45,-112.78) 54(283.45,112.78) 55(314.95,-112.78) 56(314.95,112.78) 57(346.45,-112.78) 58(346.45,112.78) 59(377.95,-112.78) 60(377.95,112.78) 61(409.43,-112.78) 62(409.43,112.78) 63(440.93,-112.78) 64(440.93,112.78) 65(472.43,-112.78) 66(472.43,112.78) 67(503.93,-112.78) 68(503.93,112.78) 69(535.42,-112.78) 70(535.42,112.78) 71(566.92,-112.78) 72(566.92,112.78) 73(598.42,-112.78) 74(598.42,112.78) 75(629.92,-112.78) 76(629.92,112.78) 77(661.42,-112.78) 78(661.42,112.78) 79(692.9,-112.78) 80(692.9,112.78)
  rect 109x16 smd: 81(-711.22,0) 84(-76.17,0) 85(76.17,0) 88(711.22,0)
  rect 185x16 smd: 82(-518.7,0) 83(-268.7,0) 86(268.7,0) 87(518.7,0)
  round 40 / inner round 60 / far side round 60 hole 40: 89(-789.95,104.92) 90(789.95,104.92)
  silkscreen extent -821,-205 821,167, body extent -812,-148 813,147, height 120
RES4-0.8 [mm] "Resistor chip array, 0.8mm spacing, 1.6mm wide, 4 pads"
  rect 0.9x0.5 smd: 1(0,0) 2(0,-0.8) 3(1.6,-0.8) 4(1.6,0)
  silkscreen extent 0.6,-1.2 1,0.4, body extent -0.01,-1.21 1.59,0.39, height 0.53
SC70 [mm] "SC-70; 6 Leads"
  rect 0.45x1.25 smd: 1(-0.65,-0.95) 2(0,-0.95) 3(0.65,-0.95) 4(0.65,0.95) 5(0,0.95) 6(-0.65,0.95)
  silkscreen extent -1.27,-1.95 1.15,0.7, body extent -1.1,-1.2 1.1,1.2, height 1.1
SMA-RA [mil] "SMA right angle PCB"
  round 85 hole 65: 1(0,0) 2(-100,-100) 2(-100,100) 2(100,-100) 2(100,100)
  silkscreen extent -160,-160 160,160, body extent -125,-460 125,125, height 375
SO-8_N [mm] "SOIC, 8-Leads, Body 4.9x3.9mm, Pitch 1.27mm, IPC Medium Density"
  oval 2.2x0.6 smd: 1(-2.4,1.905) 2(-2.4,0.635) 3(-2.4,-0.635) 4(-2.4,-1.905) 5(2.4,-1.905) 6(2.4,-0.635) 7(2.4,0.635) 8(2.4,1.905)
  silkscreen extent -2.53,-2.5 0.9,2.88, body extent -1.95,-2.45 1.95,2.45, height 1.75
SO-G3/C2.25 [mm] "SOT-23; 3 Leads; Body 3.0 x 2.5 mm, inc. leads (LxW max)"
  rect 0.95x1 smd: 1(-0.95,-1.125) 2(0.95,-1.125) 3(0,1.125)
  silkscreen extent -2.1,-1.25 1.32,1.13, body extent -1.45,-1.4 1.45,1.4, height 1.3
SO-G5/E2.4 [mm] "Small Outline; 5 Leads; Body 3.6 x 3.6 mm, inc. leads (LxW max)"
  rect 0.55x1.45 smd: 1(-0.95,-1.35) 2(0,-1.35) 3(0.95,-1.35) 4(0.95,1.35) 5(-0.95,1.35)
  silkscreen extent -1.67,-2.52 1.55,1.2, body extent -1.45,-1.4 1.45,1.4, height 1.45
SO-G8 [mm] "Small Outline; 8 Leads; Body Width 3.9 mm; Pitch 1.27 mm"
  rect 0.6x2.2 smd: 1(-1.905,-2.6) 2(-0.635,-2.6) 3(0.635,-2.6) 4(1.905,-2.6) 5(1.905,2.6) 6(0.635,2.6) 7(-0.635,2.6) 8(-1.905,2.6)
  silkscreen extent -2.88,-2.72 2.5,1.1, body extent -2.47,-3.06 2.48,3.06, height 1.75
SPSN-WSON-8_L [mm] "SON, 8-Leads, Body 6.00x8.00mm, Pitch 1.27mm, Thermal Pad 4.80x4.65mm, IPC High Density"
  oval 0.8x0.4 smd: 1(-3.84,1.905) 2(-3.84,0.635) 3(-3.84,-0.635) 4(-3.84,-1.905) 5(3.84,-1.905) 6(3.84,-0.635) 7(3.84,0.635) 8(3.84,1.905)
  rect 4.65x4.8 smd: 9(0,0)
  silkscreen extent -4.6,-3.15 4.15,3.2, body extent -4,-3 4,3, height 0.8
SSO-G8/SM8 [mm] "SSOP; 8 Leads; Body Width 2.8 mm; Pitch 0.65 mm"
  rect 0.45x1.4 smd: 1(-0.975,-1.7) 2(-0.325,-1.7) 3(0.325,-1.7) 4(0.975,-1.7) 5(0.975,1.7) 6(0.325,1.7) 7(-0.325,1.7) 8(-0.975,1.7)
  silkscreen extent -1.87,-1.82 1.6,1.7
SW_SMD_6MM [mm]
  rect 2.75x1.4 smd: 1(0,0) 2(6.8,0) 3(0,-4) 4(6.8,-4) 5(0,-2)
  silkscreen extent -2.75,-5 6.38,1
TC7343-2917 [mm] "Capacitor, D Size, Tantalum; Body 7.3 x 4.3 mm (LxW typ)"
  rect 2.6x2.4 smd: 1(-3.2,0) 2(3.2,0)
  silkscreen extent -4.58,-2.3 3.8,2.42, body extent -3.7,-2.22 3.7,2.23
TI-DBZ3_N [mm] "SOT23, 3-Leads, Body 2.92x1.3 mm, Pitch 0.95 mm, IPC Medium Density"
  rect 1.6x0.6 smd: 1(-0.9,0.95) 2(-0.9,-0.95) 3(0.9,0)
  silkscreen extent -1.02,-1.5 0.7,1.92, body extent -0.7,-1.52 0.7,1.52, height 1.12
TP1-BLK#1 [mm] "Testpoint pin, black"
  round 2.54 hole 1.58: 1(0,0)
  body extent -1.27,-1.27 1.27,1.27, height 4.89
TP1-BLK#2 [mm] "Testpoint pin, black"
  round 2.54 hole 1.58: 1(0.312,0)
  body extent -1.27,-1.27 1.27,1.27, height 4.89
TP1-RED#1 [mm] "Testpoint pin, red"
  round 2.54 hole 1.58: 1(0,0)
  body extent -1.27,-1.27 1.27,1.27, height 4.89
TP1-RED#2 [mm] "Testpoint pin, red"
  round 2.54 hole 1.58: 1(0.312,0)
  body extent -1.27,-1.27 1.27,1.27, height 4.89
TP1-WHT [mm] "Testpoint pin, white"
  round 2.54 hole 1.58: 1(0,0)
  body extent -1.27,-1.27 1.27,1.27, height 4.89
TP1-YLW#1 [mm] "Testpoint pin, yellow"
  round 2.54 hole 1.58: 1(0,-0.05)
  body extent -1.27,-1.27 1.27,1.27, height 4.89
TP1-YLW#2 [mm] "Testpoint pin, yellow"
  round 2.54 hole 1.58: 1(0,0)
  body extent -1.27,-1.27 1.27,1.27, height 4.89
TSSO3x5-G10 [mm] "Shrink Small Outline; 10 Leads; Body Width 3 mm; Pitch 0.5 mm"
  rect 0.3x1.6 smd: 1(-1,-2.05) 2(-0.5,-2.05) 3(0,-2.05) 4(0.5,-2.05) 5(1,-2.05) 6(1,2.05) 7(0.5,2.05) 8(0,2.05) 9(-0.5,2.05) 10(-1,2.05)
  silkscreen extent -1.82,-2.18 1.58,0.85, body extent -1.5,-2.54 1.5,2.49, height 1.05
TSSOP14 [mm] "Shrink Small Outline; 14 Leads; Body Width 4.4 mm; Pitch 0.65 mm"
  rect 0.3x1.65 smd: 1(-1.95,-2.775) 2(-1.3,-2.775) 3(-0.65,-2.775) 4(0,-2.775) 5(0.65,-2.775) 6(1.3,-2.775) 7(1.95,-2.775) 8(1.95,2.775) 9(1.3,2.775) 10(0.65,2.775) 11(0,2.775) 12(-0.65,2.775) 13(-1.3,2.775) 14(-1.95,2.775)
  silkscreen extent -2.77,-2.9 2.55,1.55, body extent -2.5,-3.21 2.5,3.21, height 0.94
TSSOP16 [mm] "Shrink Small Outline; 16 Leads; Body Width 4.4 mm; Pitch 0.65 mm"
  rect 0.3x1.65 smd: 1(-2.275,-2.775) 2(-1.625,-2.775) 3(-0.975,-2.775) 4(-0.325,-2.775) 5(0.325,-2.775) 6(0.975,-2.775) 7(1.625,-2.775) 8(2.275,-2.775) 9(2.275,2.775) 10(1.625,2.775) 11(0.975,2.775) 12(0.325,2.775) 13(-0.325,2.775) 14(-0.975,2.775) 15(-1.625,2.775) 16(-2.275,2.775)
  silkscreen extent -3.1,-2.9 2.55,1.55, body extent -2.5,-3.2 2.5,3.2, height 1.13
VECTRON_C5310 [mm] "Vectron VCXO, C5310 series"
  rect 3x1.3 smd: 1(0,0) 2(0,-2.54) 3(0,-5.08) 4(8.7,-5.08) 5(8.7,-2.54) 6(8.7,0)
  silkscreen extent -2.56,-9.75 9.25,4.75, body extent -0.41,-9.65 9.14,4.65, height 5.9
VISH-POWERPAKSO-8_A_V [mm] "SMD, 8-Leads, Body 6.15x5.155mm, Pitch 1.27mm"
  rect 1.27x0.61 smd: 1(-2.67,1.905) 2(-2.67,0.635) 3(-2.67,-0.635) 4(-2.67,-1.905)
  rect 1.02x0.61 smd: 5(2.795,-1.905) 6(2.795,-0.635) 7(2.795,0.635) 8(2.795,1.905)
  Top Layer region: -1.215,0.305 2.595,0.305 2.595,1.955 -1.215,1.955
  Top Layer region: -1.215,-1.955 2.595,-1.955 2.595,-0.305 -1.215,-0.305
  silkscreen extent -3.98,1.78 -3.73,2.03, body extent -3.08,-2.58 3.08,2.58, height 1.12

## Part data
C1 C3 C11: library part ChipCap, "Capacitor, surface mount", Part Number=490-1763-1-ND, Tolerance=1%, Voltage Rating=25V
C2 C4 C5 C6 C7 C9 C10 C12 C13 C14 C15 C16 C17 C18 C19 C20 C21 C22 C23 C24 C25 C26 C27 C28 C30 C31 C32 C33 C34 C35 C37 C38 C39 C40 C41 C42 C43 C44 C45 C46 C47 C48 C49 C50 C51 C52 C53 C54 C55 C56 C57 C58 C59 C60 C61 C62 C63 C64 C65 C66 C67 C68 C69 C73 C75 C76 C77 C78 C79 C80 C81 C82 C83 C84 C85 C86 C87 C89 C91 C93 C94 C95 C96 C97 C98 C99 C128 C148 C161 C165 C166 C170 C173 C174 C176 C181 C184 C185 C186 C187 C188 C189 C190 C191 C192 C193 C194 C195 C196 C197 C198 C199 C200 C201 C202 C203 C204 C205 C206 C207 C208 C209 C210: library part ChipCap, "Capacitor, surface mount", Tolerance=10%
C8: library part ChipCap, "Capacitor, surface mount", Tolerance=1%
C29: library part ChipCap, "Capacitor, surface mount", Part Number=PCC1893CT-ND, Tolerance=10%, Voltage Rating=25V
C36: library part CapFilmAxial, "Film Capacitor, axial lead", Tolerance=1%, Voltage Rating=50V
C70 C92: library part ChipCap, "Capacitor, surface mount", Part Number=490-1642-1-ND, Tolerance=10%
C71 C72: library part ChipTantalum, "Tantalum capacitor, surface mount", Part Number=399-3908-1-ND, Tolerance=20%, Voltage Rating=25V
C74: library part ChipCap, "Capacitor, surface mount", Part Number=1276-6472-1-ND, Tolerance=10%
C88: library part ChipCap, "Capacitor, surface mount", Part Number=478-1395-1-ND, Tolerance=10%
C90: library part ChipCap, "Capacitor, surface mount", Part Number=PCC2414CT-ND, Tolerance=10%, Voltage Rating=25V
C100 C183: library part ChipCap, "Capacitor, surface mount", Part Number=399-5516-1-ND, Tolerance=10%
C101 C103 C182: library part ChipCap, "Capacitor, surface mount", Part Number=587-4317-1-ND, Tolerance=10%
C102: library part ChipCap, "Capacitor, surface mount", Part Number="490-13976-1-ND (4V)", Tolerance=10%
C104 C105 C106 C107 C108 C109 C110 C111 C112 C116 C117 C118 C119 C120 C121 C167 C168 C169 C178 C179 C180: library part ChipCap, "Capacitor, surface mount", Part Number=587-5870-1-ND, Tolerance=10%
C113 C114 C115 C122 C123 C124 C125 C126 C127 C129 C130 C131 C132 C133 C134 C135 C136 C137 C138 C139 C140 C141 C142 C143 C144 C145 C146 C147 C149 C150 C151 C152 C153 C154 C155 C156 C157 C158 C159 C160 C162 C163 C164 C171 C172 C175 C177: library part CMP-2010-00306-1, Manufacturer=Samsung, Part Number=CL03A474MR3NNNC
D1 D2: library part CMP-2000-06604-1, "Ultra Low Forward Voltage Schottky Rectifier, 15 V, -55 to 100 degC, 2-Pin Molded, RoHS, Tape and Reel", Capacitance @ Vr, F=-, Current - Average Rectified (Io)=1A, Current - Reverse Leakage @ Vr=10mA@15V, Manufacturer=MicrosemiCorporation, Operating Temperature - Junction=-55°C~150°C, Package / Case=DO-214AA,SMB, Package Description="2-Pin Surface Mount Device, Body 4.315 x 3.62 mm", Package Reference=DO-214BA-2, Supplier Device Package=DO-214BA, Voltage - DC Reverse (Vr) (Max)=15V, Voltage - Forward (Vf) (Max) @ If=220mV@1A
DS1: "Panel mount LED"
DS2 DS3: library part CMP-0245-00001-1, "2.1x0.7mm Right Angle SMT LED, 1.3mm Thickness, Red", Emitting Color=Red, Forward Current="30 mA", Power Dissipation="75 mW", Reverse Voltage="5 V", Storage Temperature="-40 to 85 degC"
FL1 FL2 FL3 FL4 FL5: library part CMP-2000-05960-1, "Block Type EMIFIL(R) Reference Specification, 15 A, 25 V, -40 to 125 degC, 6-Pin THD, RoHS, Bulk", Manufacturer=Murata, Maximum Current Rating=15A, Maximum Operating Temperature=+125°C, Maximum Voltage Rating=25Vdc, Minimum Operating Temperature=-40°C, Operating Frequency=100kHz→1GHz, Package Description="6-Pin Through Hole Device, Body 12 x 11 mm"
FR1 FR2 FR3 FR4 FR5 FR6: library part BLM31PG121SN1, "ferrite bead, 120Ohm at 100MHz, 1206"
J1: "fiber optic transceiver, 1.25GB/s, MM, LC, SFP"
J2: "Connector", Manufacturer_Name=Molex, Mouser Part Number=538-45558-0003
J3: "Receptacle Assembly, 25 Position, Right Angle, .318 Series", Part Number=A32128-ND
J4: "SMA, PCB Mount, Right Angle"
L1 L8: library part ChipInductor, "Inductor", Part Number=1008LS-101XJLB
L2 L5: library part CMP-11268-000008-1, "INDUCTOR, 2.2uH", Ambient Temperature Range High=+125°C, Ambient Temperature Range Low=-40°C, Inductance=10uH, Manufacturer=Coilcraft, Manufacturer Part Number=XAL4040-103MEC, Package=XAL40, Rms Current=3.1A, Saturation Current=3A, Self Resonant Frequency=24MHz, Series Resistance=92.4mΩ, Test Frequency=1MHz, Tolerance=20%
L3: library part CMP-11268-000008-1, "INDUCTOR, 4.7uH", Ambient Temperature Range High=+125°C, Ambient Temperature Range Low=-40°C, Inductance=10uH, Manufacturer=Coilcraft, Manufacturer Part Number=XAL4040-103MEC, Package=XAL40, Rms Current=3.1A, Saturation Current=3A, Self Resonant Frequency=24MHz, Series Resistance=92.4mΩ, Test Frequency=1MHz, Tolerance=20%
L4: library part CMP-11268-000008-1, "INDUCTOR, 3.3uH", Ambient Temperature Range High=+125°C, Ambient Temperature Range Low=-40°C, Inductance=10uH, Manufacturer=Coilcraft, Manufacturer Part Number=XAL4040-103MEC, Package=XAL40, Rms Current=3.1A, Saturation Current=3A, Self Resonant Frequency=24MHz, Series Resistance=92.4mΩ, Test Frequency=1MHz, Tolerance=20%
L6 L7: library part ChipInductor, "Inductor"
LOGO1: library part LIGO_logo
P1: library part CMP-2000-05512-1, "Economy Version Right Angle D-Sub Connector, 5 A, -55 to 105 degC, 37-Pin THD, RoHS, Tray", Color=Black, Current Rating=5A, Manufacturer=Norcomp, Operating Temperature=-55°C~105°C, Package Description="37-Pin Connector, Body 69.32 x 12.42 mm, Pitch 1.385 mm", Package Version="03/2005, Rev. 9", Standard Package=40, Voltage Rating=-
P2: "Flat Cable Connector (IDC), PCB Transition Connector, 2 Rows, Solder Pin, 8 Contacts", PackageDocument=26-Nov-2003
P3: library part Xilinx_JTAG_Header, "Xilinx JTAG header, 7-Pin, Dual row", Part Number=WM4224-ND
P4: library part CMP-0001-00030-1, "Golden finger, PCIeX1, Dual, Opposite, Pitch 1mm, 36-Position"
P5 P6: library part SAMTEC_QSE40, "Samtec hi-speed socket, 0.8mm, 80 pins", Manufacturer=Samtec, Part Number=SAM8124-ND
Q1 Q5 Q6: "FDV301N, Digital FET, N-channel, SOT23", Part Number=FDV301NCT-ND
Q2 Q3: library part CMP-1048-00670-1, "General Purpose Transistor, PNP Silicon, 3-Pin SOT-23, Pb-Free, Tape and Reel", Manufacturer="On Semiconductor"
Q4: library part CMP-2000-07602-1, "Dual N-Channel (D-S) MOSFET, 100 V, 36.7 A, -55 to 150 degC, 8-Pin SMD, RoHS, Tape and Reel", Manufacturer="Vishay Semiconductor", Package Description="8-Pin Surface Mount Device, Body 6.15 x 5.155 mm, Pitch 1.27 mm", Package Reference=POWERPAKSO-8
R1 R2 R5 R6 R10 R12 R16 R17 R18 R20 R21 R22 R23 R24 R25 R26 R27 R28 R29 R30 R31 R32 R33 R34 R35 R36 R37 R38 R39 R40 R41 R42 R43 R44 R48 R49 R50 R51 R52 R53 R54 R55 R56 R57 R58 R59 R60 R61 R62 R63 R64 R65 R66 R67 R68 R69 R70 R71 R72 R73 R74 R75 R76 R77 R78 R79 R80 R81 R82 R83 R84 R85 R86 R87 R88 R89 R90 R91 R92 R93 R94 R95 R96 R97 R98 R99 R101 R103 R104 R105 R106 R107 R108 R109 R111 R112 R113 R114 R115 R116 R117 R118 R119 R120 R121 R122 R123 R124 R125 R126 R129 R130 R131 R132 R133 R134 R141 R142 R144 R156 R159 R162 R163 R166 R167 R168 R169 R170 R171 R174 R175 R176 R179 R180 R181 R182 R183 R185 R186 R187 R188 R189 R190 R191 R192 R193 R194 R195 R196 R197 R198 R199 R200 R201 R202: library part ChipRes1, "Resistor, surface mount", Tolerance=1%
R3 R4 R7 R8 R9 R11 R13 R15 R135 R137 R138 R140 R143 R145 R146 R147 R148 R149 R150 R151 R152 R153 R184: library part ChipRes1, "Resistor, surface mount", Tolerance=0.1%
R14: library part ChipRes1, "Resistor, surface mount", Part Number=RG20P100KBCT-ND, Tolerance=0.1%
R19 R45: library part Res2, "Resistor", Part Number=RR12P26.1KBCT-ND, Tolerance=0.1%
R46 R47 R136 R139: library part Res2, "Resistor", Part Number=RR12P1.0KBCT-ND, Tolerance=0.1%
R100: library part ChipRes1, "Resistor, surface mount", Part Number=311-200FRCT-ND, Tolerance=1%
R102: library part ChipRes1, "Resistor, surface mount", Part Number=311-0.0ERCT-ND, Tolerance=1%
R110: library part RES2_ARRAY, "Resistor Network, parallel, 2 resistors"
R127: library part ChipRes1, "Resistor, surface mount", Part Number=RG20P7.15KBCT-ND, Tolerance=0.1%
R128: library part ChipRes1, "Resistor, surface mount", Part Number=RG20P1.0KBCT-ND, Tolerance=0.1%
R154 R155 R157 R158 R160 R161 R164 R165 R172 R173 R177 R178: library part ChipRes1, "Resistor, surface mount", Part Number=RR12P100DCT-ND, Tolerance=0.5%
S1: "DIP Switch, 8 Position, SPST", Part Number=CKN6128CT-ND
S2: "Switch, SMD, 6mm", Part Number=SW262CT-ND
T1: library part TC1.5-52, "Transformer 1:4, wide band, 0.5-300 MHz", Part Number=TC1-1TX+
TP1 TP3 TP7 TP9 TP10 TP12 TP15 TP19 TP21 TP22 TP25: library part TP_POSITIVE, "Testpoint, red", Part Number=5005K-ND
TP2 TP5: library part TP_NEGATIVE, "Testpoint, white", Part Number=5007K-ND
TP4 TP6 TP8 TP13 TP14 TP18 TP20 TP23 TP24: library part TP_GND, "Testpoint, black", Part Number=5006K-ND
TP11 TP16 TP17 TP26: library part TP_SIGNAL, "Testpoint, yellow", Part Number=5009K-ND
U1 U5 U6 U8 U9: library part CMP-0944-00088-2, "Low Power, Precision Instrumentation Amplifier, -40 to 125 degC, 8-pin SOP (DGK8), Green (RoHS & no Sb/Br)", Input Bias Current (+/-)(Max)(nA)=0.2, Manufacturer="Texas Instruments", Quiescent Current (+/-)(Typ)(mA)=0.05
U2: library part CMP-0798-00217-1, "1.8 to 5.5 V / 2.5 V, CMOS Low-Voltage 2.5 Ohm, 16-Channel Multiplexer, -40 to 85 degC, 28-pin SOP (RU-28), Tube", Manufacturer="Analog Devices"
U3: "Precision Rail-to-Rail Input and Ouput Operational Amplifier"
U4 U24 U28: "Precision Rail-to-Rail Input and Output Operational Amplifier"
U7 U10: library part SN74AHCT04D, "Hex Inverter", Part Number=296-1218-1-ND
U11 U12: "16 bit DAC, 250kSPS, unipolar, serial"
U13 U23: library part 74F74PC, "Dual D-Type Positive Edge-Triggered Flip-Flop", Part Number=296-1240-5-ND
U14: "Quad LVDS Receiver with 100 Ohm termination"
U15: "Quad-Bit Dual Supply Transceiver"
U16: library part CMP-0383-00019-1, "Artix-7 FPGA, 250 User I/Os, 4 GTP, 484-Ball BGA, Speed Grade 2, Commercial Grade, Pb-Free", Manufacturer=Xilinx, Operating Temperature Range=Commercial
U17: library part CMP-0327-00205-3, "125 Mbps Enhanced Product Memorystick? Interconnect Extender Chipset with LVDS and LVTTL, 1 Tx and 4 Rx, -55 to +125 degC, 20-pin TSSOP (PW), Green (RoHS & no Sb/Br)", Manufacturer="Texas Instruments"
U18: library part CMP-12948-000005-1, "IC FLASH 128M SPI 133MHZ 16SOIC", Ambient Temperature Range High=+85°C, Ambient Temperature Range Low=-40°C, Frequency=133MHz, Manufacturer="Cypress Semiconductor", Max Supply Voltage=3.6V, Min Supply Voltage=1.65V, Nominal Supply Current=16-100mA, Package=002-15547, Temperature="-40°C to +85°C"
U19: "Switched capacitor voltage inverter"
U20: library part CMP-1329-00027-1, "MirrorBit Flash Non-Volatile Memory CMOS 3.0 Volt Core with Versatile I/O, Serial Peripheral Interface with Multi-I/O, 128 Mbit, 133 MHz, -40 to 85 degC, 8-Pin WSON (WNG008), RoHS, Tape and Reel", Manufacturer=Spansion, Temperature Range="-40 to 85 degC"
U21: library part CMP-0384-00702-1, "Double Channel Single-Supply Operation Operational Amplifier, 4.25 MHz BW, 4 V/us SR, Industrial, 8-pin SOIC (R-8), Tube", Amplifiers Per Package=2, Generic Part Number=OP284, Input Bias Current=80nA, Input Offset Voltage=175uV, Manufacturer="Analog Devices"
U22: "16 bit ADC, 250kSPS, pseudo differential, serial"
U25: Part Number=296-9845-1-ND
U26: "Artix 7 Power Supply", Manufacturer_Part_Number=ADP5052ACPZ-R7
U27: library part VECTRON_C5310, "Voltage controlled crystal oscillator", Part Number=C5310-D105-SV033-RFL-B1-33.554432MHz
U29 U32: library part SN65LVDS100, "DIFF TRANSLATOR", Part Number=296-13624-5-ND
U30: library part SN65LVDT2DBV, "Single LVDS Receiver with 100 Ohm termination", Part Number=296-6896-1-ND
U31: library part ADR292ER, "Low-Noise Micropower Precision Voltage Reference", Part Number=ADR425BRZ-ND
U33: library part SN65LVDS100, "DIFF TRANSLATOR", Part Number=296-15391-5-ND
U34: "Positive voltage regulator", Part Number=LT1763CS8#PBF-ND
U35 U39: library part SN65LVDT2DBV, "Single LVDS Receiver with 100 Ohm termination"
U36 U37: "20V, 500mA, Ultralow Noise, / Ultrahigh PSRR Linear Regulator", Part Number=LT3045EMSE#PBF-ND
U38: library part SN74LVC1T45, "Single-Bit Dual Supply Transceiver"
U40: library part CMP-0367-00169-1, "3.3 V, 50 ppm / degC, 50 uA Series (Bandgap) Voltage Reference, -40 to 125 degC, 3-pin SOT-23 (DBZ), Green (RoHS & no Sb/Br)", Manufacturer="Texas Instruments", Rating=Catalog, Temp Coeff(Max)(ppm/ degree C)=50, Temp Coeff(Typ)(ppm/ degree C)=20
U41: library part CMP-0476-01338-1, "200 mA, Low Noise, Low Dropout Negative Micropower Regulator, -1.9 to -20 V Vin, -5 V Vout, 5-pin SOT23 (S5-5), -40 to 125 degC, Pb-Free, Mini Tape and Reel", Dropout Voltage(V)=0.34, Manufacturer="Linear Technology", Output Voltage="-5 V", PartNumber=LT1964ES5-5#TRMPBF, Shutdown Current(uA)=3
U42: library part CMP-0784-00214-1, "Ultraprecision, Low Noise, XFET(R) Voltage Reference, 2.5 V Output, 4.5 to 18 V Supply, Industrial, 8-pin SOIC (R-8), Tube", Manufacturer="Analog Devices", Operating Temp Range="-40 to 125 degC"
U43: "Positive voltage regulator"
W1: library part NetTie1, "Tie two nets together"
W2: library part NetTie1_small, "Tie two nets together"
Y1: library part CMP-06255-000005-1, "MEMS OSC XO 25.0000MHZ CMOS SMD", Ambient Temperature Range High=+85°C, Ambient Temperature Range Low=-40°C, Frequency=25MHz, Manufacturer="Microchip Technology", Max Junction Temp=+150°C, Max Supply Voltage=3.6V, Min Supply Voltage=1.7V, Package=CDFN2520-4LD-PL-1, Temperature="-40°C to +85°C"

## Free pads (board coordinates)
  round 4.826 hole 3.175: 0(-17.38,-28.28) 0(-17.38,47.92) 0(33.42,-28.28) 0(33.42,47.92)
  round 2.88 hole 3.18 unplated: MH1(-74.75,-49.65) MH2(-74.5,35.75)

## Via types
v1: diameter 0.483, hole 0.254, Top Layer to Bottom Layer, tented both sides, 740 vias
v2: diameter 0.508, hole 0.254, Top Layer to Bottom Layer, tented both sides, 302 vias
v3: diameter 0.406, hole 0.254, Top Layer to Bottom Layer, tented both sides, 267 vias
v4: diameter 0.305, hole 0.152, Top Layer to Bottom Layer, tented both sides, 95 vias
v5: diameter 0.5, hole 0.254, Top Layer to Bottom Layer, tented both sides, 50 vias
v6: diameter 0.45, hole 0.254, Top Layer to Bottom Layer, tented both sides, 23 vias
v7: diameter 0.6, hole 0.254, Top Layer to Bottom Layer, tented both sides, 14 vias

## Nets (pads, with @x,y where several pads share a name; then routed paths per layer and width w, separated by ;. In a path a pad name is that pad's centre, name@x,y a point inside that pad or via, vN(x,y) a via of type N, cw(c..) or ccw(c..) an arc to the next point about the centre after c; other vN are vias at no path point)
3.3Vaux: P4.B10 | length 3.1
  Top Layer w0.203: P4.B10@-27.35,-55.5 -27.35,-52.85 v6(-27,-52.5)
12V: C28.1 C29.1 C43.1 C44.1 C58.1 C59.1 C76.2 C79.1 FL2.1 FL5.1 P6.77 P6.79 R37.2 R47.2 R99.2 R136.1 R141.1 R142.2 TP19.1 U19.8 U21.8 U26.4 U26.9 U26.24 U26.25 U26.35 U26.36 | length 80
  Top Layer w0.127: R47.2@40,-9.65 40.537,-10.186 40.887,-10.186 41,-10.3 42.8,-10.3 47.3,-14.8 61.634,-14.8 67.434,-9 71.95,-9 73.15,-7.8 R99.2@73.7,-7.8
  Top Layer w0.203: C43.1@48,-31.775 48.025,-31.75 U26.9@50.075,-31.75 ; C44.1@48,-29.275 48.025,-29.25 U26.4@50.075,-29.25 ; U26.35@56.925,-28.25 U26.36@56.925,-27.75 56.934,-27.741 57.359,-27.741 57.7,-27.4 57.7,-26.848 57.999,-26.55 C59.1@58.2,-26.55
  Top Layer w0.254: U26.24@56.25,-33.925 56.925,-33.925 ; U26.25@56.925,-33.25 56.925,-33.925 ; 57.552,-33.925 56.925,-33.925 ; C58.1@57.652,-34.077 C58.1@58.1,-34.525
  Top Layer w0.35: P6.77@24.82,42.515 v1(24.82,44.051) ; P6.79@25.62,42.515 v1(25.62,44.051)
  Top Layer w0.5: R37.2@26.95,-43 26.905,-42.955 U19.8@26.905,-41.1 26.955,-41.05 26.955,-40.245 27.7,-39.5 28.975,-39.5 C28.1@29,-39.475 ; U21.8@30.6,-12.405 30.654,-12.405 30.7,-12.451 v2(30.7,-13.5) v2(31.2,-13.5) 31.202,-13.5 31.452,-13.75 31.9,-13.75 C29.1@32.15,-14
  Top Layer w1: R99.2@73.7,-7.8 74.066,-7.8 74.366,-7.5 74.366,-2.634 FL5.1@74.5,-2.5
  Bottom Layer w0.203: R142.2@-4.952,-38.4 -4.848,-38.4 -4.15,-39.098 R141.1@-4.15,-41
  Bottom Layer w1: R142.2@-5,-38.4 -4.952,-38.4 ccw(c-4.952,-35.86) -3.156,-37.656 FL2.1@-1.5,-36 ccw(c-2.707,-34.793) -1,-34.793 R136.1@-1,-33.45 ; FL5.1@74.5,-2.5 74.5,-2.689 75.6,-3.789 C76.2@75.6,-7
  other v2: 28.6,-40.4 29,-40.4 29.4,-40.4
  other v4: 57.6,-33.721 58.1,-33.721 58.6,-33.721 47.15,-32.25 47.15,-32 47,-29.4 47,-28.875 57.728,-27.213 58.2,-27.213 58.7,-27.213
+3.3V: C187.1 P4.A9 P4.A10 P4.B8 R147.2 U38.6 | length 31.2
  Top Layer w0.203: P4.B8@-29.35,-55.5 -29.35,-53.05 -28.894,-52.594 v6(-28.35,-52.594)
  Int7 (Sign) w0.3: v6(-28.35,-52.594) -28.35,-48.952 cw(c-25.81,-48.952) -27.606,-47.156 v6(-19.65,-39.2)
  Bottom Layer w0.203: P4.A9@-28.2,-55.35 P4.A9@-28.35,-55.5 v6(-28.35,-52.594) -27.796,-52.594 -27.35,-53.04 P4.A10@-27.35,-55.5
  Bottom Layer w0.3: C187.1@-20.85,-36.5 -19.65,-36.5 U38.6@-19.65,-36.95 R147.2@-19.65,-38.5 v6(-19.65,-39.2)
A12V: C71.1 C72.1 C88.2 FL5.2 U34.5 U34.8 | length 61.9
  Top Layer w2: FL5.2@74.5,2.5 80.2,8.2 C71.1@80.2,15.5 C72.1@80.2,20.526
  Bottom Layer w0.5: v2(39.5,5.4) 39.502,5.4 39.507,5.405 40,5.405 40.5,5.405 U34.5@42.6,5.405 45.195,5.405 46.975,3.625 C88.2@46.975,3.5 ; U34.8@42.6,1.595 45.195,1.595 C88.2@46.975,3.375
  Bottom Layer w1: C88.2@46.975,3.375 C88.2@46.975,3.5 48.5,3.5 49.5,2.5 FL5.2@74.5,2.5
  other v2: 40,5.4 40.5,5.4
